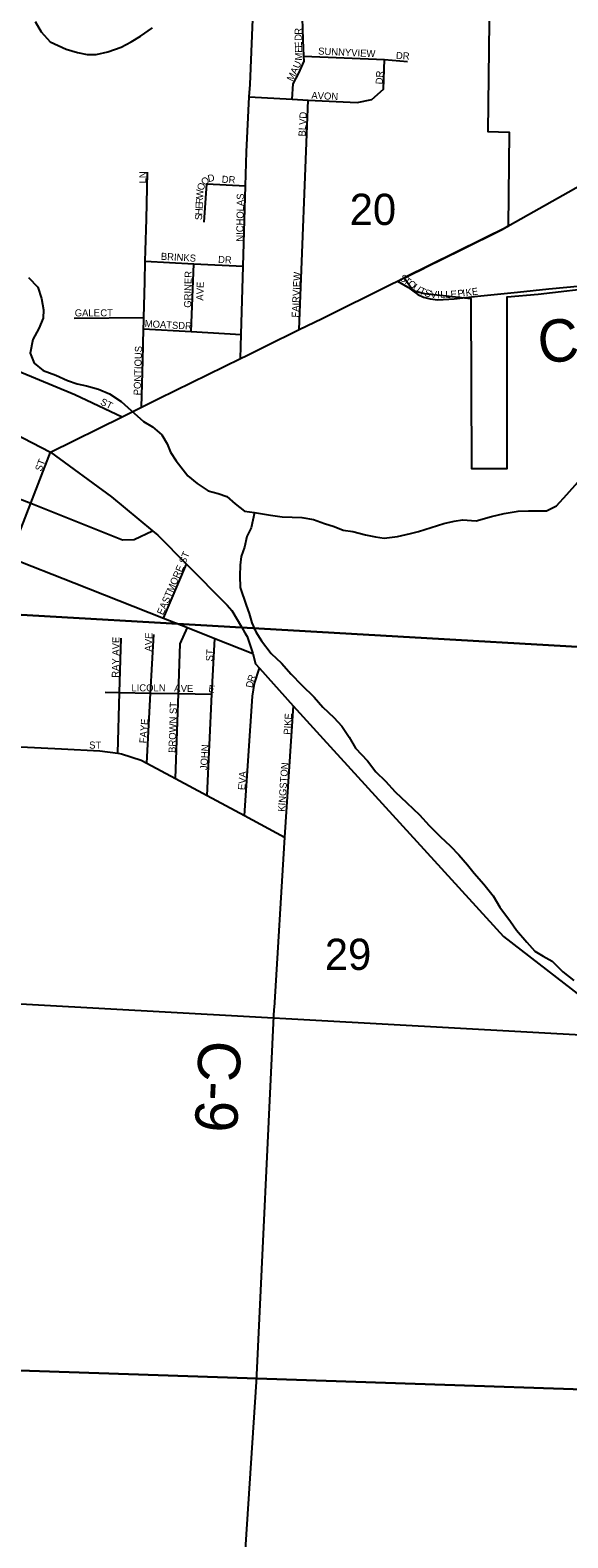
# Model space of a CAD drawing. Extents: x 1643459 to 2064572, y 425441 to 780708.
# Drawn here: x 1846132 to 1849935, y 574746 to 585413 of the extents above; entities that cross this region are included whole.
import ezdxf

# ---------------------------------------------------------------- set-up
doc = ezdxf.new("R2010")
doc.units = 0
for name, color, linetype in [('GM_X_Adjacent_County', 7, 'Continuous'), ('GM_X_Airport_Class_2', 7, 'Continuous'), ('GM_X_Airport_Class_3', 7, 'Continuous'), ('GM_X_Minor_Lake', 7, 'Continuous'), ('GM_X_Rail_Line_Text', 7, 'Continuous'), ('GM_X_Section_Text', 7, 'Continuous'), ('GM_X_State_Route', 7, 'Continuous'), ('GM_X_US_Route', 7, 'Continuous'), ('RD_X_Text', 7, 'Continuous'), ('RD_X_Wall', 7, 'Continuous')]:
    doc.layers.add(name, color=color, linetype=linetype)

msp = doc.modelspace()

# ---------------------------------------------------------------- linework, layer by layer
at = {"layer": 'GM_X_Airport_Class_2'}
for points in [[(1847620, 583090), (1847625, 583259), (1847639, 583743), (1847655, 584313), (1847662, 584553), (1847682, 584941), (1847687, 585030), (1847707, 585492), (1847713, 585595), (1847732, 585953), (1847760, 586444), (1847781, 586657), (1847807, 586925), (1847809, 586968), (1847830, 587323), (1847833, 587380), (1847828, 587634), (1847820, 588027), (1847813, 588398), (1847805, 588841)], [(1847986, 584925), (1847993, 585033), (1848032, 585109), (1848069, 585193), (1848067, 585229), (1848062, 585345), (1848057, 585576)], [(1847682, 584941), (1847986, 584925), (1848099, 584919), (1848445, 584901), (1848548, 584922), (1848631, 584996), (1848638, 585206)], [(1848067, 585229), (1848638, 585206), (1848800, 585191)], [(1848035, 583295), (1848099, 584919)], [(1846954, 584076), (1846954, 584076), (1846962, 584409)], [(1847363, 584055), (1847381, 584327), (1847655, 584313)], [(1846948, 583854), (1846948, 583854), (1846954, 584076)], [(1846942, 583632), (1846942, 583632), (1846946, 583779), (1846948, 583854)], [(1846946, 583779), (1847290, 583761), (1847639, 583743)], [(1847270, 583281), (1847290, 583761)], [(1848730, 583637), (1848803, 583594), (1848873, 583542), (1848913, 583524), (1848962, 583512), (1849015, 583506), (1849132, 583512), (1849274, 583529), (1849319, 583533)], [(1846935, 583355), (1846935, 583355), (1846936, 583380), (1846942, 583632)], [(1846443, 583376), (1846936, 583380)], [(1846928, 583077), (1846928, 583077), (1846934, 583301), (1846935, 583355)], [(1846934, 583301), (1847270, 583281), (1847625, 583259)], [(1842782, 583008), (1843529, 582652), (1843993, 582469), (1844858, 582128), (1845363, 581929), (1845988, 581682), (1846443, 581502)], [(1845909, 583059), (1845918, 583055), (1846447, 582836), (1846782, 582677)], [(1846919, 582745), (1846928, 583077)], [(1845980, 581662), (1845988, 581682), (1846136, 582066), (1846275, 582427)], [(1846002, 582119), (1846136, 582066), (1846786, 581808), (1846867, 581809), (1846998, 581871), (1847003, 581873)], [(1847074, 581253), (1847238, 581635)], [(1846443, 581502), (1846443, 581502), (1847074, 581253), (1847074, 581253)], [(1847074, 581253), (1847244, 581186), (1847438, 581110), (1847706, 581004)], [(1847160, 580118), (1847180, 580720), (1847192, 581072), (1847244, 581186)], [(1846752, 580297), (1846764, 580727), (1846775, 581111)], [(1846956, 580228), (1846983, 580723), (1847006, 581137)], [(1847383, 579998), (1847418, 580716), (1847438, 581110)], [(1847648, 579856), (1847704, 580700), (1847719, 580791), (1847754, 580898)], [(1846662, 580729), (1846763, 580727)], [(1846763, 580727), (1846764, 580727), (1846983, 580723), (1847180, 580720), (1847418, 580716)], [(1847991, 580633), (1847932, 579703), (1847857, 578495)], [(1845728, 580358), (1845728, 580358), (1846354, 580328), (1846354, 580328)], [(1846354, 580328), (1846625, 580315), (1846752, 580297), (1846777, 580294), (1846917, 580249), (1846956, 580228), (1847160, 580118), (1847383, 579998), (1847648, 579856), (1847932, 579703)]]:
    msp.add_lwpolyline(points, dxfattribs=at)
at = {"layer": 'GM_X_Minor_Lake'}
for points in [[(1849578, 583560), (1849800, 583583), (1850232, 583624), (1850541, 583651), (1850771, 583660), (1850876, 583662)], [(1849319, 583533), (1849578, 583560)], [(1847857, 578495), (1847856, 578487), (1847730, 575849), (1847618, 574122), (1847566, 573349), (1847466, 572254), (1847414, 571424), (1847396, 571127), (1847373, 570967), (1847316, 570803), (1847249, 570616)]]:
    msp.add_lwpolyline(points, dxfattribs=at)
at = {"layer": 'GM_X_Rail_Line_Text'}
for points in [[(1849387, 586251), (1849370, 584697), (1849520, 584692), (1849514, 584024), (1848778, 583661), (1848840, 583572), (1848922, 583549), (1849249, 583515), (1849254, 582311), (1849505, 582311), (1849505, 583526), (1849726, 583545), (1850170, 583598)], [(1850625, 578270), (1845164, 578572), (1845146, 577994), (1842490, 578131), (1841189, 578262), (1841161, 578061), (1840908, 578095), (1840877, 577953), (1840747, 577963), (1840631, 578804), (1840511, 578802), (1840661, 577797), (1840712, 577343), (1840742, 577116), (1840743, 576186), (1844935, 576115), (1844914, 574790), (1843401, 574814), (1843401, 574798), (1842708, 574809), (1842708, 574826), (1842329, 574832), (1842064, 574740)]]:
    msp.add_lwpolyline(points, dxfattribs=at)
at = {"layer": 'GM_X_State_Route'}
for points in [[(1845707, 586588), (1851086, 586327), (1850782, 581006), (1845371, 581316)], [(1850782, 581006), (1850463, 575781), (1845006, 575965), (1845371, 581316)], [(1845006, 575965), (1850463, 575781), (1850117, 570449), (1849865, 570458), (1844677, 570773)]]:
    msp.add_lwpolyline(points, close=True, dxfattribs=at)
at = {"layer": 'GM_X_US_Route'}
for points in [[(1846167, 585474), (1846209, 585401), (1846273, 585330), (1846386, 585280), (1846466, 585255), (1846536, 585240), (1846598, 585242), (1846682, 585260), (1846775, 585293), (1846847, 585331), (1846913, 585370), (1846996, 585430)], [(1846120, 583664), (1846186, 583595), (1846213, 583515), (1846227, 583434), (1846223, 583376), (1846192, 583302), (1846150, 583224), (1846131, 583128), (1846159, 583057), (1846224, 583005), (1846314, 582972), (1846396, 582935), (1846464, 582911), (1846530, 582896), (1846616, 582874), (1846692, 582839)], [(1846692, 582839), (1846775, 582785), (1846847, 582722), (1846933, 582645), (1846998, 582606), (1847064, 582550), (1847102, 582487), (1847125, 582427), (1847165, 582365), (1847246, 582260), (1847314, 582205), (1847392, 582154), (1847462, 582134), (1847524, 582113), (1847583, 582063), (1847647, 582010), (1847719, 582000), (1847831, 581981), (1847915, 581970), (1847985, 581968), (1848053, 581964), (1848135, 581951), (1848215, 581922), (1848283, 581902), (1848347, 581875), (1848415, 581865), (1848505, 581842), (1848575, 581828), (1848635, 581819), (1848731, 581831), (1848821, 581852), (1848879, 581866), (1848969, 581895), (1849057, 581923), (1849132, 581940), (1849190, 581948), (1849286, 581942), (1849396, 581973), (1849484, 581994), (1849584, 582010), (1849656, 582013), (1849784, 582013), (1849855, 582048), (1849929, 582128), (1850006, 582216)], [(1847719, 582000), (1847694, 581892), (1847664, 581830), (1847648, 581755), (1847625, 581689), (1847617, 581629), (1847614, 581553), (1847618, 581471), (1847659, 581344), (1847681, 581286), (1847700, 581219), (1847728, 581157), (1847768, 581092), (1847837, 581004), (1847909, 580935), (1847978, 580856), (1848052, 580781), (1848141, 580693), (1848201, 580624), (1848279, 580551), (1848336, 580489), (1848388, 580412), (1848433, 580333), (1848517, 580243), (1848578, 580166), (1848646, 580099), (1848714, 580023), (1848797, 579946), (1848887, 579861), (1848954, 579786), (1849032, 579708), (1849106, 579639), (1849163, 579578), (1849225, 579508), (1849272, 579449), (1849342, 579370), (1849408, 579288), (1849455, 579209), (1849529, 579106), (1849572, 579046), (1849644, 578961), (1849701, 578896), (1849761, 578862), (1849825, 578827), (1849899, 578751), (1849978, 578688)]]:
    msp.add_lwpolyline(points, dxfattribs=at)
at = {"layer": 'RD_X_Text'}
for points in [[(1846275, 582427), (1846706, 582111), (1846998, 581871), (1847036, 581840), (1847238, 581635), (1847525, 581346), (1847559, 581308), (1847626, 581192)], [(1847626, 581192), (1847651, 581149), (1847667, 581122), (1847706, 581004), (1847726, 580929), (1847754, 580898), (1847991, 580633), (1848204, 580399)], [(1848204, 580399), (1849481, 579001), (1850156, 578477), (1850234, 578403)]]:
    msp.add_lwpolyline(points, dxfattribs=at)
at = {"layer": 'RD_X_Wall'}
for points in [[(1849528, 584035), (1850401, 584529), (1850982, 584820), (1851014, 584835)], [(1849180, 583859), (1849470, 584002), (1849528, 584035)], [(1842751, 583882), (1842760, 583878), (1843083, 583767), (1843844, 583446), (1844311, 583262), (1845116, 582938), (1845881, 582631), (1846275, 582427)], [(1848930, 583736), (1849180, 583859)], [(1848197, 583374), (1848686, 583615), (1848730, 583637), (1848915, 583728), (1848930, 583736)], [(1847797, 583177), (1848035, 583295), (1848197, 583374), (1848197, 583374)], [(1847620, 583090), (1847664, 583112), (1847797, 583177)], [(1847043, 582806), (1847620, 583090)], [(1846275, 582427), (1846782, 582677), (1846919, 582745), (1847043, 582806), (1847043, 582806)]]:
    msp.add_lwpolyline(points, dxfattribs=at)

# ---------------------------------------------------------------- texts
at = {"layer": 'GM_X_Adjacent_County'}
for s, p in [('20', (1848392, 584035)), ('29', (1848216, 578764))]:
    msp.add_text(s, height=221, rotation=0, dxfattribs=at).set_placement(p)
at = {"layer": 'GM_X_Airport_Class_3'}
for s, rotation, p in [('R', 90.0243, (1848053, 585381)), ('D', 90.5902, (1848053, 585338)), ('E', 92.1585, (1848055, 585289)), ('M', 87.5056, (1848054, 585197)), ('E', 92.2903, (1848056, 585254)), ('SUNNYVIEW', 357.2727, (1848168, 585241)), ('DR', 356.989, (1848718, 585210)), ('A', 65.0874, (1848014, 585096)), ('U', 67.9682, (1848034, 585138)), ('M', 62.0175, (1847988, 585046)), ('DR', 86.989, (1848625, 585029)), ('AVON', 357.1392, (1848120, 584928)), ('BLVD', 86.9887, (1848079, 584660)), ('LN', 90, (1846953, 584329)), ('D', 12.0129, (1847393, 584338)), ('DR', 356.989, (1847486, 584334)), ('W', 87.1356, (1847355, 584222)), ('O', 72.1111, (1847357, 584275)), ('O', 42.062, (1847367, 584311)), ('E', 87.1356, (1847351, 584147)), ('R', 87.1356, (1847353, 584182)), ('NICHOLAS', 89.1789, (1847639, 583916)), ('S', 87.1356, (1847347, 584068)), ('H', 87.1356, (1847349, 584103)), ('BRINKS', 356.6353, (1847055, 583789)), ('DR', 356.989, (1847460, 583767)), ('GRINER', 88.8947, (1847270, 583449)), ('FAIRVIEW', 87.4721, (1848031, 583379)), ('S', 323.6874, (1848741, 583650)), ('T', 323.6492, (1848769, 583630)), ('O', 323.6707, (1848798, 583609)), ('AVE', 88.0186, (1847356, 583499)), ('U', 323.6721, (1848833, 583583)), ('T', 335.3942, (1848878, 583551)), ('S', 343.3568, (1848917, 583534)), ('V', 354.5189, (1848962, 583521)), ('I', 359.5626, (1849010, 583517)), ('L', 1.664, (1849034, 583517)), ('L', 2.3533, (1849070, 583518)), ('E', 4.1684, (1849107, 583519)), ('P', 7.2107, (1849158, 583524)), ('I', 7.313, (1849193, 583528)), ('K', 7.3139, (1849215, 583531)), ('E', 7.2877, (1849259, 583537)), ('GALE', 0, (1846447, 583388)), ('CT', 0, (1846628, 583388)), ('MOATS', 356.4984, (1846941, 583313)), ('DR', 356.989, (1847178, 583300)), ('PONTIOUS', 88.3406, (1846913, 582829)), ('ST', 333.435, (1846623, 582767)), ('ST', 68.1961, (1846210, 582287)), ('EASTMORE ST', 66.6448, (1847072, 581271)), ('RAY AVE', 89.0613, (1846759, 580831)), ('AVE', 87.9557, (1846992, 581016)), ('ST', 86.4126, (1847424, 580946)), ('LICOLN', 0, (1846848, 580735)), ('A', 355.2291, (1847149, 580735)), ('V', 359.4521, (1847197, 580731)), ('E', 359.9956, (1847241, 580731)), ('E', 351.8743, (1847390, 580731)), ('D', 79.0501, (1847705, 580757)), ('R', 70.3053, (1847713, 580798)), ('BROWN ST', 88.3873, (1847160, 580299)), ('FAYE', 85.2389, (1846953, 580366)), ('PIKE', 86.3038, (1847974, 580427)), ('ST', 0, (1846549, 580330)), ('JOHN', 86.7313, (1847384, 580176)), ('KINGSTON', 85.971, (1847934, 579882)), ('EVA', 86.0574, (1847652, 580035))]:
    msp.add_text(s, height=50, rotation=rotation, dxfattribs=at).set_placement(p)
at = {"layer": 'GM_X_Section_Text'}
for s, rotation, p in [('C-40', 5.4097, (1849736, 583054)), ('C-9', 267.2517, (1847326, 578269))]:
    msp.add_text(s, height=300, rotation=rotation, dxfattribs=at).set_placement(p)

doc.saveas('drawing.dxf')
